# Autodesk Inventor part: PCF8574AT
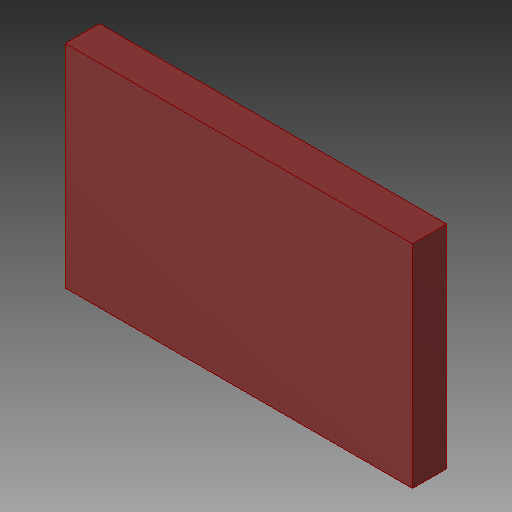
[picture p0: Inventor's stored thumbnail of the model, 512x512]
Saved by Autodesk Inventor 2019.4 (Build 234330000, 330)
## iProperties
Created: 2019-11
Part Number: PCF8574AT
Material: Generic
Document SubType Name: Modeling
Designer: Willist
Density: 1 g/cm^3
Appearance: SO16, PCF8574AT
Author: Willist
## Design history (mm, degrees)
sketch "SO16, PCF8574AT_31"
  geometry: L1 (-5.08, 3.099)-(5.08, 3.099); L2 (5.08, 3.099)-(5.08, -3.099); L3 (5.08, -3.099)-(-5.08, -3.099); L4 (-5.08, -3.099)-(-5.08, 3.099)
  constraints: 8 end point
extrude "Extrusion1" join sketch "SO16, PCF8574AT_31" distance "d0" = 1; taper "d1" = 0 deg
body "Solid1"
